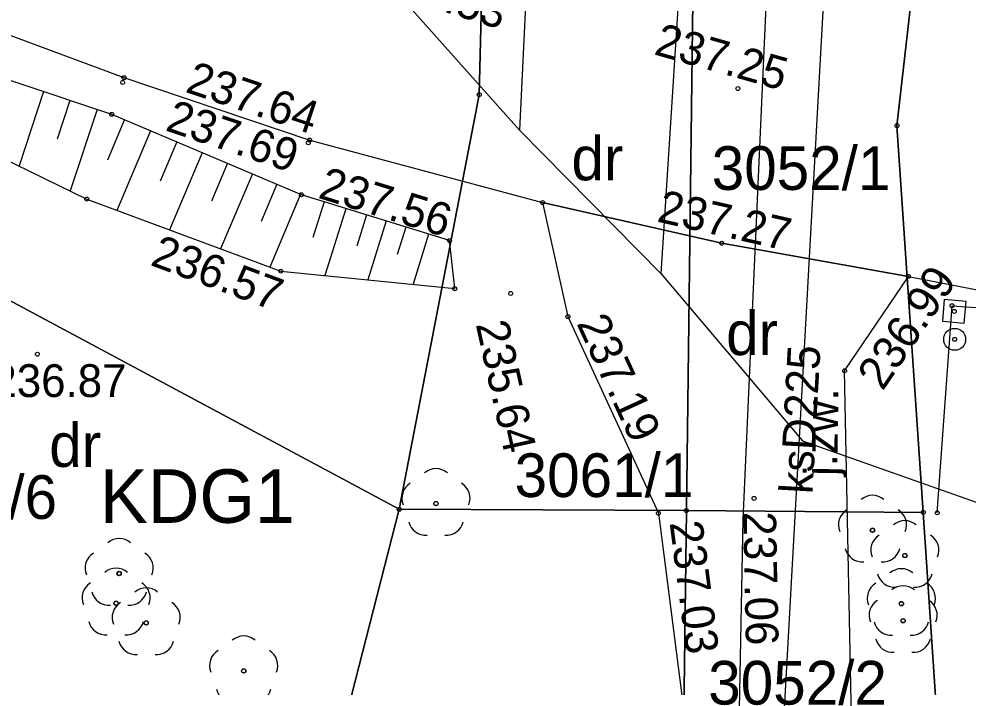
# Model space of a CAD drawing. Extents: x 6596400 to 6597200, y 5539751 to 5540251.
# Drawn here: x 6596703.94 to 6596725.66, y 5540079.07 to 5540094.36 of the extents above; entities that cross this region are included whole.
import ezdxf

# ---------------------------------------------------------------- set-up
doc = ezdxf.new("R2010")
doc.units = 0
for name, color, linetype in [('000 Inne (niezydentyfikowane)', 7, 'Continuous'), ('140-Punkty robocze', 7, 'Continuous'), ('203-punkt graniczny', 7, 'Continuous'), ('210-oznaczenie konturu użytku gruntowego', 7, 'Continuous'), ('211-numer działki ewidencyjnej', 7, 'Continuous'), ('218-kontur użytku gruntowego', 7, 'Continuous'), ('219-działka ewidencyjna', 7, 'Continuous'), ('bariera ochronna', 7, 'Continuous'), ('drzewo liściaste', 7, 'Continuous'), ('jezdnia', 7, 'Continuous'), ('jezdnia-Atr17', 7, 'Continuous'), ('krawężnik', 7, 'Continuous'), ('Linia obszaru zagospodarowania terenu', 7, 'Continuous'), ('Opis obszaru zagospodarowania terenu', 7, 'Continuous'), ('pikieta sztuczna', 7, 'Continuous'), ('pikieta sztuczna-Atr2', 7, 'Continuous'), ('przewód kanalizacyjny', 7, 'Continuous'), ('przewód kanalizacyjny-Atr1', 7, 'Continuous'), ('skarpa nieumocniona', 7, 'Continuous'), ('właz do komory lub kanału - kwadratowy', 7, 'Continuous'), ('właz do komory lub kanału - okrągły', 7, 'Continuous')]:
    doc.layers.add(name, color=color, linetype=linetype)

# ---------------------------------------------------------------- blocks, each defined once
blk = doc.blocks.new('203')
blk.add_circle((0, 0), 0.045)
blk = doc.blocks.new('OP021')
blk.add_circle((0, 0), 0.05)
for centre, start, end in [((0, 0.4), 49.272, 130.728), ((-0.38, 0.124), 121.308, 202.548), ((0.38, 0.124), 337.452, 58.692), ((-0.235, -0.324), 193.221, 274.871), ((0.235, -0.324), 265.129, 346.779)]:
    blk.add_arc(centre, 0.4, start, end)
blk = doc.blocks.new('US22')
blk.add_circle((0, 0), 0.25)
blk = doc.blocks.new('US22A')
blk.add_lwpolyline([(-0.25, -0.25), (0.25, -0.25), (0.25, 0.25), (-0.25, 0.25)], close=True)
blk = doc.blocks.new('PW01')
blk.add_circle((0, 0), 0.045)
blk = doc.blocks.new('PIKIETA')
blk.add_circle((0, 0), 0.045)

msp = doc.modelspace()

# ---------------------------------------------------------------- linework, layer by layer
at = {"layer": '000 Inne (niezydentyfikowane)'}
for points in [[(6596704.5, 5540092.7), (6596703.94, 5540091)], [(6596705.1, 5540092.5), (6596704.81, 5540091.61)], [(6596705.73, 5540092.29), (6596705.11, 5540090.43)], [(6596706.35, 5540092.06), (6596705.96, 5540091.13)], [(6596706.95, 5540091.8), (6596706.18, 5540089.98)], [(6596707.55, 5540091.55), (6596707.17, 5540090.65)], [(6596708.13, 5540091.3), (6596707.38, 5540089.54)], [(6596708.71, 5540091.06), (6596708.34, 5540090.19)], [(6596709.28, 5540090.82), (6596708.55, 5540089.1)], [(6596709.84, 5540090.58), (6596709.48, 5540089.73)], [(6596710.38, 5540090.35), (6596709.68, 5540088.68)], [(6596710.92, 5540090.18), (6596710.66, 5540089.36)], [(6596711.42, 5540090.02), (6596710.94, 5540088.49)], [(6596711.89, 5540089.88), (6596711.67, 5540089.16)], [(6596712.34, 5540089.74), (6596711.92, 5540088.39)], [(6596712.79, 5540089.6), (6596712.59, 5540088.97)], [(6596713.31, 5540089.44), (6596712.96, 5540088.29)]]:
    msp.add_lwpolyline(points, dxfattribs=at)
at = {"layer": '218-kontur użytku gruntowego'}
for points in [[(6596725.02, 5540100.61), (6596724.03, 5540091.92)], [(6596724.03, 5540091.92), (6596725.02, 5540100.61)], [(6596714.65, 5540099.99), (6596714.47, 5540092.63)], [(6596714.47, 5540092.63), (6596714.65, 5540099.99)], [(6596719.42, 5540099.7), (6596719.21, 5540083.11)], [(6596719.21, 5540083.11), (6596719.42, 5540099.7)], [(6596712.64, 5540083.14), (6596682.08, 5540099.52)], [(6596682.08, 5540099.52), (6596712.64, 5540083.14)], [(6596714.47, 5540092.63), (6596712.64, 5540083.14)], [(6596712.64, 5540083.14), (6596714.47, 5540092.63)], [(6596724.03, 5540091.92), (6596724.63, 5540083.07)], [(6596724.63, 5540083.07), (6596724.03, 5540091.92)], [(6596710.04, 5540072.97), (6596712.64, 5540083.14)], [(6596712.64, 5540083.14), (6596710.04, 5540072.97)], [(6596712.64, 5540083.14), (6596719.21, 5540083.11)], [(6596719.21, 5540083.11), (6596712.64, 5540083.14)], [(6596719.21, 5540083.11), (6596719.13, 5540076.68)], [(6596719.13, 5540076.68), (6596719.21, 5540083.11)], [(6596724.63, 5540083.07), (6596719.21, 5540083.11)], [(6596719.21, 5540083.11), (6596724.63, 5540083.07)], [(6596724.63, 5540083.07), (6596725.18, 5540074.87)], [(6596725.18, 5540074.87), (6596724.63, 5540083.07)]]:
    msp.add_lwpolyline(points, dxfattribs=at)
at = {"layer": '219-działka ewidencyjna'}
for points in [[(6596724.03, 5540091.92), (6596725.02, 5540100.61)], [(6596714.47, 5540092.63), (6596714.65, 5540099.99)], [(6596719.21, 5540083.11), (6596719.42, 5540099.7)], [(6596712.64, 5540083.14), (6596682.08, 5540099.52)], [(6596712.64, 5540083.14), (6596714.47, 5540092.63)], [(6596724.63, 5540083.07), (6596724.03, 5540091.92)], [(6596710.04, 5540072.97), (6596712.64, 5540083.14)], [(6596712.64, 5540083.14), (6596719.21, 5540083.11)], [(6596719.13, 5540076.68), (6596719.21, 5540083.11)], [(6596719.21, 5540083.11), (6596724.63, 5540083.07)], [(6596725.18, 5540074.87), (6596724.63, 5540083.07)]]:
    msp.add_lwpolyline(points, dxfattribs=at)
at = {"layer": 'bariera ochronna'}
msp.add_lwpolyline([(6596724.95, 5540083.06), (6596725.29, 5540087.8), (6596726.8, 5540087.69), (6596748.55, 5540083.38), (6596760.42, 5540081.05)], dxfattribs=at)
at = {"layer": 'jezdnia'}
for points in [[(6596653.124, 5540120.82), (6596653.79, 5540120.41), (6596660.56, 5540116.72), (6596663.8, 5540114.85), (6596668, 5540112.34), (6596669.54, 5540111.42), (6596675.97, 5540107.49), (6596679.93, 5540105.19), (6596682.35, 5540103.89), (6596691.43, 5540099.24), (6596702.2, 5540094.56), (6596706.34, 5540093.02), (6596710.59, 5540091.59), (6596715.92, 5540090.16), (6596720.02, 5540089.23), (6596724.29, 5540088.47), (6596726.93, 5540087.96), (6596734.57, 5540086.51), (6596738.41, 5540085.75), (6596741.83, 5540085.11), (6596743.38, 5540084.84), (6596743.64, 5540085.7), (6596748.72, 5540084.9)], [(6596722.99, 5540078.36), (6596722.83, 5540086.31), (6596724.29, 5540088.47), (6596720.02, 5540089.23), (6596715.92, 5540090.16), (6596716.5, 5540087.55), (6596718.57, 5540083.05), (6596719.35, 5540076.97), (6596719.16, 5540072.77), (6596716.97, 5540066.06), (6596715.072, 5540062.675)]]:
    msp.add_lwpolyline(points, dxfattribs=at)
at = {"layer": 'krawężnik'}
msp.add_lwpolyline([(6596653.124, 5540120.82), (6596653.79, 5540120.41), (6596660.56, 5540116.72), (6596663.8, 5540114.85), (6596668, 5540112.34), (6596669.54, 5540111.42), (6596675.97, 5540107.49), (6596679.93, 5540105.19), (6596682.35, 5540103.89), (6596691.43, 5540099.24), (6596702.2, 5540094.56), (6596706.34, 5540093.02), (6596710.59, 5540091.59)], dxfattribs=at)
at = {"layer": 'Linia obszaru zagospodarowania terenu'}
for points in [[(6596664.616, 5540132.112), (6596671.21, 5540127.95), (6596681.8, 5540121.54), (6596690.35, 5540115.69), (6596701.61, 5540105.97), (6596709.34, 5540098.61), (6596715.39, 5540091.82), (6596718.63, 5540088.53), (6596721.87, 5540084.71), (6596726.1, 5540083.21), (6596730.7, 5540082.79), (6596730.91, 5540075), (6596745.51, 5540074.64), (6596746.77, 5540082.74), (6596765.15, 5540085.09), (6596776.62, 5540086.27), (6596789.34, 5540086.1), (6596798.37, 5540085.54), (6596805.65, 5540083.56), (6596813.11, 5540081.53), (6596819.41, 5540077.54), (6596826.58, 5540072.81), (6596832.721, 5540067.998)], [(6596717.208, 5540120.978), (6596716.13, 5540107.22), (6596715.39, 5540091.82)], [(6596718.63, 5540088.53), (6596719.66, 5540104.62), (6596720.915, 5540121.024)]]:
    msp.add_lwpolyline(points, dxfattribs=at)
at = {"layer": 'przewód kanalizacyjny'}
for points in [[(6596723.203, 5540121.052), (6596721.45, 5540104.04), (6596720.5, 5540082.91), (6596720.2, 5540067.11), (6596715.44, 5540062.371)], [(6596724.65, 5540121.069), (6596722.94, 5540105.56), (6596720.82, 5540067.29), (6596715.895, 5540061.995)]]:
    msp.add_lwpolyline(points, dxfattribs=at)
at = {"layer": 'skarpa nieumocniona'}
msp.add_lwpolyline([(6596678.95, 5540103.44), (6596684.48, 5540100.39), (6596690.52, 5540096.75), (6596701.2, 5540092.33), (6596705.49, 5540090.24), (6596709.93, 5540088.59), (6596713.91, 5540088.19), (6596713.79, 5540089.29), (6596710.4, 5540090.34), (6596706.06, 5540092.18), (6596701.79, 5540093.6), (6596690.99, 5540097.77), (6596684.6, 5540101.39), (6596679.33, 5540104.04), (6596675.06, 5540106.16)], close=True, dxfattribs=at)
msp.add_lwpolyline([(6596678.95, 5540103.44), (6596684.48, 5540100.39), (6596690.52, 5540096.75), (6596701.2, 5540092.33), (6596705.49, 5540090.24), (6596709.93, 5540088.59), (6596713.91, 5540088.19), (6596713.79, 5540089.29), (6596710.4, 5540090.34), (6596706.06, 5540092.18), (6596701.79, 5540093.6), (6596690.99, 5540097.77), (6596684.6, 5540101.39), (6596679.33, 5540104.04), (6596675.06, 5540106.16)], close=True, dxfattribs=at)

# ---------------------------------------------------------------- block references
at = {"layer": '140-Punkty robocze'}
for p in [(6596706.31, 5540092.91), (6596706.34, 5540093.02), (6596706.06, 5540092.18), (6596705.49, 5540090.24), (6596715.92, 5540090.16), (6596713.79, 5540089.29), (6596724.29, 5540088.47), (6596713.91, 5540088.19), (6596725.29, 5540087.8), (6596725.34, 5540087.67), (6596725.35, 5540087.03), (6596722.83, 5540086.31), (6596713.48, 5540083.27), (6596724.95, 5540083.06), (6596723.47, 5540082.66), (6596724.21, 5540082.08), (6596706.23, 5540081.67), (6596706.16, 5540080.99), (6596724.13, 5540080.98), (6596706.85, 5540080.54), (6596724.17, 5540080.59), (6596709.08, 5540079.44)]:
    msp.add_blockref('PIKIETA', p, dxfattribs=at)
at = {"layer": '203-punkt graniczny'}
for p in [(6596714.47, 5540092.63), (6596724.03, 5540091.92), (6596712.64, 5540083.14), (6596719.21, 5540083.11), (6596724.63, 5540083.07)]:
    msp.add_blockref('203', p, dxfattribs=at)
at = {"layer": 'drzewo liściaste'}
for p in [(6596713.48, 5540083.27), (6596723.47, 5540082.66), (6596724.21, 5540082.08), (6596706.23, 5540081.67), (6596706.16, 5540080.99), (6596724.13, 5540080.98), (6596724.17, 5540080.59), (6596706.85, 5540080.54), (6596709.08, 5540079.44)]:
    msp.add_blockref('OP021', p, dxfattribs=at)
at = {"layer": 'pikieta sztuczna'}
for p in [(6596720.39, 5540092.77), (6596710.59, 5540091.59), (6596710.56, 5540091.53), (6596710.4, 5540090.34), (6596720.02, 5540089.23), (6596709.93, 5540088.59), (6596715.19, 5540088.08), (6596716.5, 5540087.55), (6596704.36, 5540086.69), (6596722.83, 5540086.31), (6596720.76, 5540083.39), (6596718.57, 5540083.05)]:
    msp.add_blockref('PW01', p, dxfattribs=at)
at = {"layer": 'właz do komory lub kanału - kwadratowy', "rotation": -4.97000000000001}
msp.add_blockref('US22A', (6596725.34, 5540087.67), dxfattribs=at)
at = {"layer": 'właz do komory lub kanału - okrągły'}
msp.add_blockref('US22', (6596725.35, 5540087.03), dxfattribs=at)

# ---------------------------------------------------------------- texts
at = {"layer": '210-oznaczenie konturu użytku gruntowego'}
for p in [(6596716.58, 5540090.67), (6596720.12, 5540086.67), (6596704.63, 5540084.11)]:
    msp.add_text('dr', height=1, dxfattribs=at).set_placement(p)
at = {"layer": '211-numer działki ewidencyjnej'}
for s, p in [('3052/1', (6596719.79, 5540090.45)), ('3061/1', (6596715.28, 5540083.42)), ('3011/6', (6596700.72, 5540082.92)), ('3052/2', (6596719.71, 5540078.67))]:
    msp.add_text(s, height=1, dxfattribs=at).set_placement(p)
at = {"layer": 'jezdnia-Atr17'}
msp.add_text('j.zw.', height=0.75, rotation=89.063, dxfattribs=at).set_placement((6596722.66, 5540083.9))
msp.add_text('j.zw.', height=0.75, rotation=89.063, dxfattribs=at).set_placement((6596722.66, 5540083.9))
at = {"layer": 'Opis obszaru zagospodarowania terenu'}
msp.add_text('KDG1', height=1.225, dxfattribs=at).set_placement((6596705.79, 5540082.83))
at = {"layer": 'pikieta sztuczna-Atr2'}
for s, rotation, p in [('237.53', 342.391, (6596712.033, 5540095.045)), ('237.25', 344.159, (6596718.445, 5540093.558)), ('237.64', 341.403, (6596707.721, 5540092.699)), ('237.69', 341.403, (6596707.261, 5540091.819)), ('237.56', 342.79, (6596710.758, 5540090.274)), ('237.27', 347.22, (6596718.514, 5540089.729)), ('236.57', 339.614, (6596706.919, 5540088.737)), ('236.99', 55.944, (6596723.701, 5540085.83)), ('237.19', 294.702, (6596716.689, 5540087.397)), ('235.64', 282.529, (6596714.388, 5540087.377)), ('237.06', 271.153, (6596720.51, 5540083.085)), ('237.03', 277.311, (6596718.826, 5540082.835))]:
    msp.add_text(s, height=0.75, rotation=rotation, dxfattribs=at).set_placement(p)
msp.add_text('236.87', height=0.75, dxfattribs=at).set_placement((6596703.33, 5540085.71))
at = {"layer": 'przewód kanalizacyjny-Atr1'}
msp.add_text('ksD225', height=0.75, rotation=86.829, dxfattribs=at).set_placement((6596722.094, 5540083.479))

doc.saveas('drawing.dxf')
